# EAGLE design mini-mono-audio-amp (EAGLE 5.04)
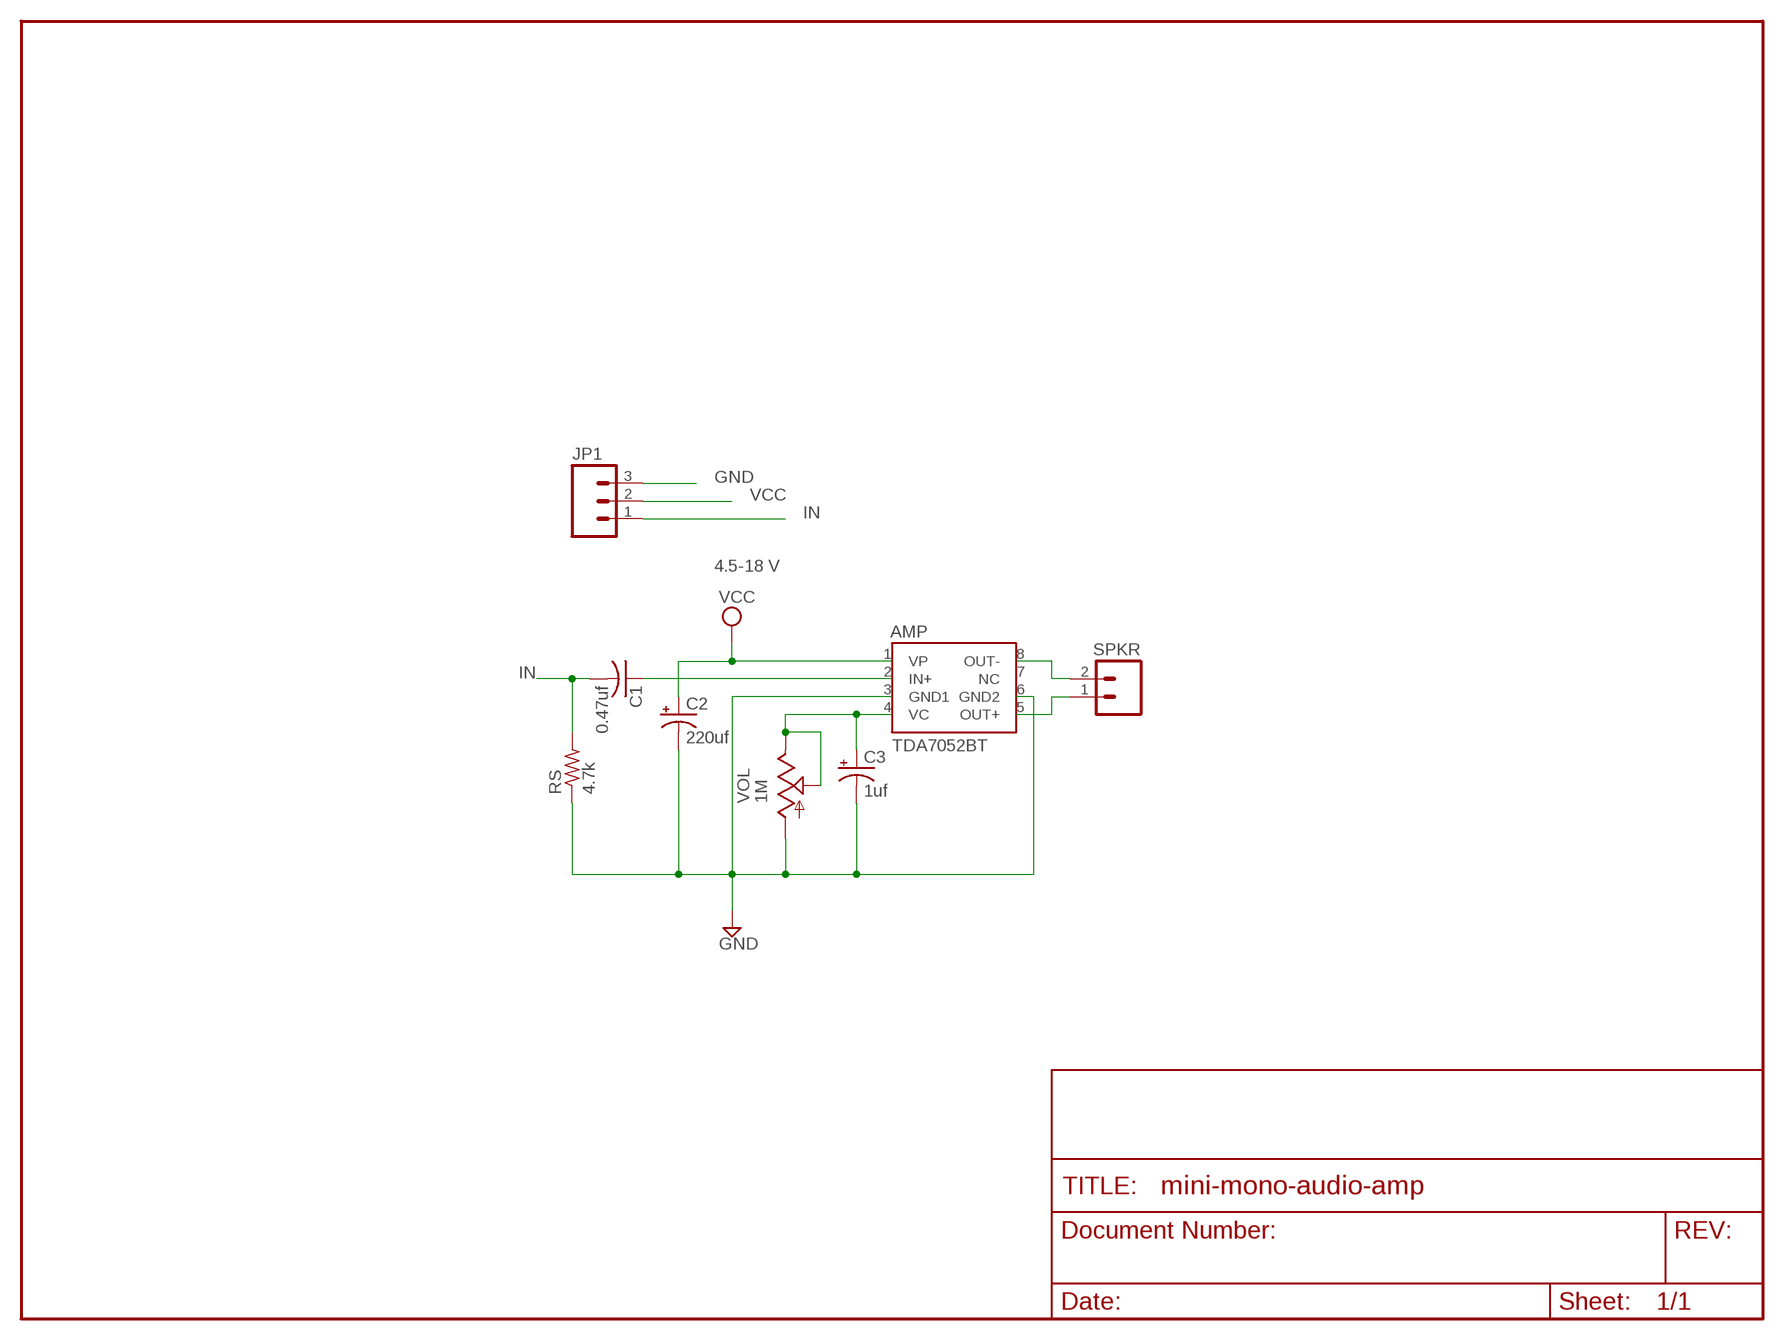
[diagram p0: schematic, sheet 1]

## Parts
AMP  TDA7052BT  [8SOIC]
C1  0.47uf  C-US050-024X044  [C050-024X044]
C2  220uf  CPOL-USB45181C  [B45181C]
C3  1uf  CPOL-USB45181C  [B45181C]
JP1  M03POLAR  [MOLEX-1X3]
RS  4.7k  R-US_0204/7  [0204/7]
SPKR  M02PTH  [1X02]
VOL  1M  POT-TRIM-PARALLAX  [POT-TRIM-PARALLAX]

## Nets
GND: AMP.3(GND1) AMP.6(GND2) C2.- C3.- JP1.3 RS.1 VOL.1(A)
IN: C1.2 JP1.1 RS.2
N$1: AMP.2(IN+) C1.1
N$3: AMP.4(VC) C3.+ VOL.2(S) VOL.3(E)
N$4: AMP.5(OUT+) SPKR.1
N$5: AMP.8(OUT-) SPKR.2
VCC: AMP.1(VP) C2.+ JP1.2
Unconnected: AMP.7(NC)

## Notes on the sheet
- 4.5-18 V

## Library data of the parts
AMP = trl:TDA7052BT
C1 = rcl:C-US: CAPACITOR, American symbol
C2 C3 = resistor:CPOL-US: POLARIZED CAPACITOR, American symbol
JP1 = SparkFun:M03: Header 3 Standard 3-pin 0.1" header. Use with straight break away headers (SKU : PRT-00116), right angle break away headers (PRT-00553), swiss pins (PRT-00743), machine pins (PRT-00117), and female headers (PRT-00115). Molex polarized connector foot print use with SKU : PRT-08232 with associated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
RS = rcl:R-US_: RESISTOR, American symbol
SPKR = SparkFun:M02: Header 2
VOL = trl:POT-TRIM-PARALLAX: POTENTIOMETER

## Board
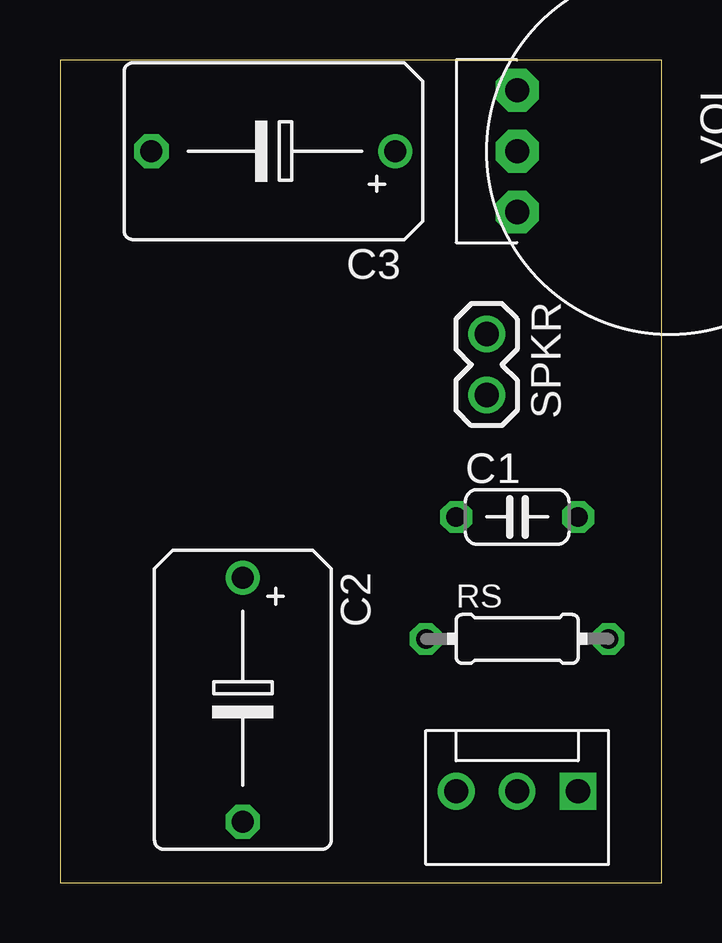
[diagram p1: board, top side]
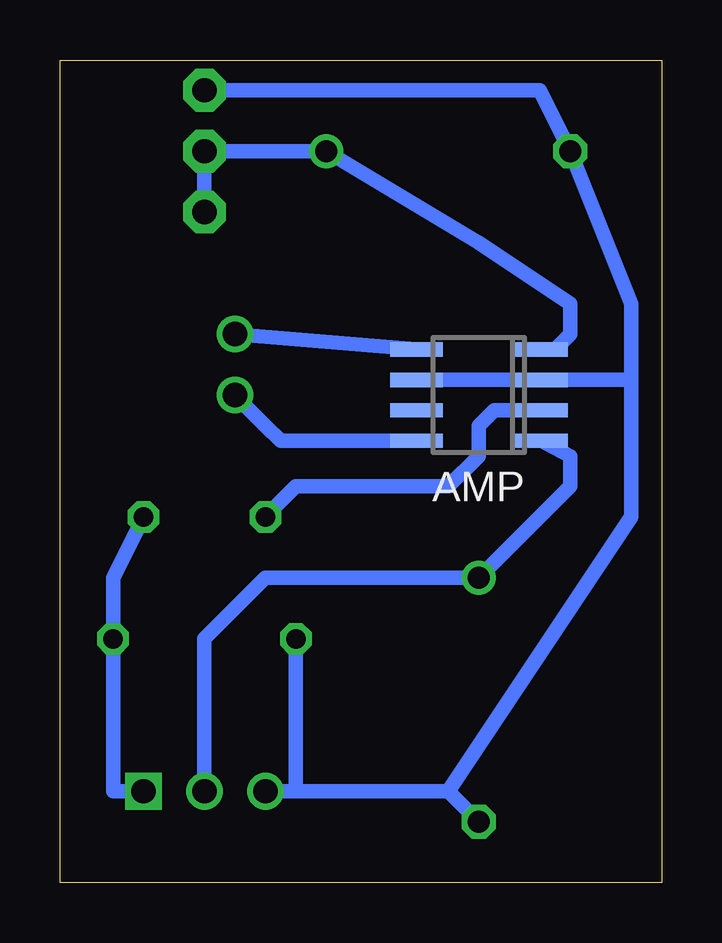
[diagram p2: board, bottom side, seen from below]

Size 25.07 x 34.28 mm. Coordinates in mm from the lower left corner, seen from the top.
Outline: 0,0 25.07,0 25.07,34.28 0,34.28 0,0
Copper layers (1*16): Top 0.035mm / dielectric 1.5mm / Bottom 0.035mm
Design rules "default": minimum track width 10mil, minimum drill 24mil, track to track 8mil, track to pad 8mil, pad to pad 8mil, via to via 8mil, smd to smd 8mil, copper to edge 40mil, drill to drill 8mil, minimum pad ring 10mil, minimum via ring 8mil, stop-mask expansion 4mil, vias tented up to drill 0mil, thermal gap 10mil

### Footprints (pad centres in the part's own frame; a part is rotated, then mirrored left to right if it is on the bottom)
8SOIC = smd 0.6 x 2.2: 1 -1.905,-2.6; 2 -0.635,-2.6; 3 0.635,-2.6; 4 1.905,-2.6; 5 1.905,2.6; 6 0.635,2.6; 7 -0.635,2.6; 8 -1.905,2.6
C050-024X044 = drill 0.813 octagon: 1 -2.54,0; 2 2.54,0
B45181C = drill 0.914 round: + -5.08,0 | drill 0.914 octagon: - 5.08,0
MOLEX-1X3 = drill 1.016 square: 1 0,0 | drill 1.016 round: 2 2.54,0; 3 5.08,0
0204/7 = drill 0.813 octagon: 1 -3.81,0; 2 3.81,0
1X02 = drill 1.016 round: 1 0,0; 2 2.54,0
POT-TRIM-PARALLAX = drill 1.016 pad 1.778 octagon: 1 -2.54,-3.81; 2 0,-3.81; 3 2.54,-3.81

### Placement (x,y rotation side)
AMP  7.62,20.32 90 bottom
C1  19.05,15.24 0 top
C2  7.62,7.62 270 top
C3  8.89,30.48 180 top
JP1  21.59,3.81 180 top
RS  19.05,10.16 0 top
SPKR  17.78,22.86 270 top
VOL  22.86,30.48 270 top

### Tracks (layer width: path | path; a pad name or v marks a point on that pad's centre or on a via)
GND
  Bottom 0.61: 15.24,3.81 RS.1 | 15.24,3.81 JP1.3 | C2.- 8.89,3.81 | 8.89,3.81 15.24,3.81 | VOL.1 15.24,33.02 5.08,33.02 C3.- 1.27,24.13 1.27,20.32 | 8.89,3.81 1.27,15.24 1.27,20.32 | AMP.6 AMP.3 1.27,20.95 1.27,20.32
IN
  Bottom 0.61: JP1.1 22.86,3.81 RS.2 22.86,12.7 C1.2
N$1
  Bottom 0.61: AMP.2 6.99,19.68 7.62,19.05 7.62,17.78 8.89,16.51 15.24,16.51 C1.1
N$3
  Bottom 0.61: VOL.3 VOL.2 C3.+ 7.62,26.67 3.81,24.13 3.81,22.86 4.45,22.23 AMP.4
N$4
  Bottom 0.61: SPKR.1 AMP.5
N$5
  Bottom 0.61: SPKR.2 16.51,19.05 15.88,18.41 AMP.8
VCC
  Bottom 0.61: JP1.2 19.05,10.16 16.51,12.7 C2.+ 3.81,16.51 3.81,17.78 AMP.1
